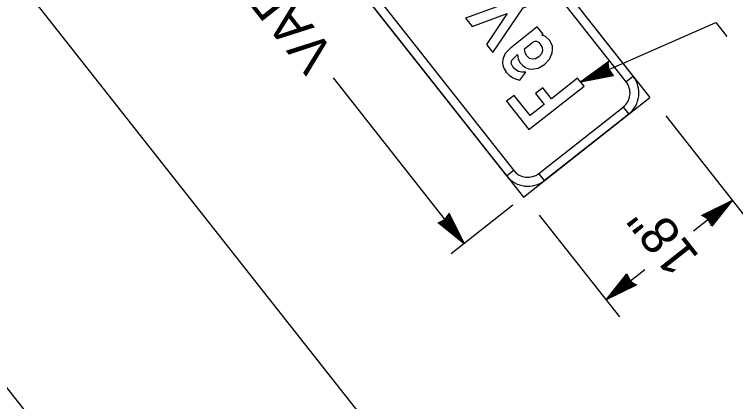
# Model space of a CAD drawing. Extents: x 672126 to 673696, y 1673540 to 1674900.
# Drawn here: x 672217.5 to 672298.2, y 1674587.2 to 1674630.5 of the extents above; entities that cross this region are included whole.
import ezdxf

# ---------------------------------------------------------------- set-up
doc = ezdxf.new("R2010")
doc.units = 0
for name, color, linetype in [('61', 7, 'Continuous'), ('C-ANNO-SYMB', 7, 'Continuous'), ('Level 1', 7, 'Continuous'), ('V-SIGNAL-LOOP', 7, 'Continuous')]:
    doc.layers.add(name, color=color, linetype=linetype)

msp = doc.modelspace()

# ---------------------------------------------------------------- linework, layer by layer
at = {"layer": '61'}
msp.add_lwpolyline([(672259.689, 1674581.406), (672186.159, 1674674.677), (672163.206, 1674656.582), (672236.736, 1674563.312)], close=True, dxfattribs=at)
at = {"layer": 'C-ANNO-SYMB'}
for p, q in [((672247.706, 1674673.092), (672288.567, 1674621.261)), ((672233.571, 1674661.948), (672274.431, 1674610.117)), ((672286.71, 1674623.617), (672285.924, 1674622.998)), ((672274.431, 1674610.117), (672288.567, 1674621.261)), ((672285.592, 1674620.189), (672286.211, 1674619.404)), ((672273.359, 1674613.092), (672272.574, 1674612.473)), ((672276.787, 1674611.975), (672276.168, 1674612.76))]:
    msp.add_line(p, q, dxfattribs=at)
for points in [[(672285.924, 1674622.998), (672248.778, 1674670.117), (672249.564, 1674670.736), (672286.71, 1674623.617), (672285.924, 1674622.998), (672285.924, 1674622.998)], [(672236.213, 1674660.211), (672273.359, 1674613.092), (672272.574, 1674612.473), (672235.428, 1674659.592), (672236.213, 1674660.211), (672236.213, 1674660.211)], [(672276.595, 1674632.098), (672275.794, 1674632.989), (672267.961, 1674630.13), (672268.701, 1674629.191), (672272.617, 1674630.656), (672270.294, 1674627.171), (672270.999, 1674626.277), (672274.405, 1674631.287)], [(672281.214, 1674622.512), (672280.498, 1674623.42), (672277.564, 1674621.108), (672276.59, 1674622.344), (672275.778, 1674621.705), (672276.753, 1674620.468), (672275.182, 1674619.23), (672273.4, 1674621.491), (672272.554, 1674620.824), (672275.052, 1674617.655)], [(672276.168, 1674612.76), (672285.592, 1674620.189), (672286.211, 1674619.404), (672276.787, 1674611.975), (672276.168, 1674612.76), (672276.168, 1674612.76)]]:
    msp.add_lwpolyline(points, close=True, dxfattribs=at)
for points in [[(672276.627, 1674628.33), (672275.99, 1674629.139), (672272.99, 1674626.774), (672272.412, 1674626.18), (672272.115, 1674625.539), (672272.084, 1674625.174), (672272.14, 1674624.814), (672272.287, 1674624.452), (672272.521, 1674624.096), (672272.842, 1674623.755), (672273.203, 1674623.492), (672273.608, 1674623.305), (672274.049, 1674623.194), (672274.704, 1674624.072), (672274.275, 1674624.074), (672273.893, 1674624.162), (672273.57, 1674624.339), (672273.3, 1674624.599), (672273.081, 1674625.036), (672273.147, 1674625.422), (672273.763, 1674626.073), (672273.857, 1674625.529), (672274.072, 1674625.11), (672274.354, 1674624.815), (672274.662, 1674624.603), (672275.005, 1674624.469), (672275.373, 1674624.413), (672276.099, 1674624.536), (672276.805, 1674624.945), (672277.351, 1674625.531), (672277.649, 1674626.235), (672277.705, 1674626.625), (672277.672, 1674626.993), (672277.555, 1674627.339), (672277.35, 1674627.661), (672276.919, 1674628.083), (672276.503, 1674628.233), (672276.627, 1674628.33)], [(672274.573, 1674626.711), (672275.521, 1674627.459), (672275.716, 1674627.557), (672275.914, 1674627.551), (672276.118, 1674627.439), (672276.325, 1674627.223), (672276.536, 1674626.851), (672276.575, 1674626.475), (672276.453, 1674626.122), (672276.169, 1674625.814), (672275.791, 1674625.587), (672275.441, 1674625.523), (672275.121, 1674625.625), (672274.827, 1674625.893), (672274.634, 1674626.263), (672274.573, 1674626.711)]]:
    msp.add_lwpolyline(points, dxfattribs=at)
for centre, radius, start, end in [((672284.354, 1674621.76), 3, 308.25039, 38.2506), ((672284.354, 1674621.76), 2, 308.25039, 38.2506), ((672274.93, 1674614.331), 2, 218.25075, 308.25039), ((672274.93, 1674614.331), 3, 218.25075, 308.25039)]:
    msp.add_arc(centre, radius, start, end, dxfattribs=at)
at = {"layer": 'Level 1'}
for p, q in [((672283.973, 1674625.266), (672280.853, 1674622.996)), ((672283.794, 1674624.956), (672281.211, 1674623.102)), ((672283.837, 1674625.12), (672281.368, 1674623.201)), ((672283.802, 1674624.815), (672281.761, 1674623.409)), ((672283.802, 1674624.815), (672281.904, 1674623.415)), ((672283.875, 1674624.904), (672283.794, 1674624.956)), ((672284.052, 1674624.068), (672283.802, 1674624.815)), ((672284.103, 1674623.887), (672283.802, 1674624.815)), ((672283.857, 1674624.755), (672283.837, 1674625.12)), ((672284.019, 1674624.397), (672283.857, 1674624.755)), ((672283.921, 1674625.127), (672283.875, 1674624.904)), ((672284.027, 1674624.314), (672283.921, 1674625.127)), ((672281.761, 1674623.409), (672284.004, 1674623.986)), ((672282.299, 1674623.62), (672282.686, 1674623.909)), ((672283.77, 1674624.629), (672282.406, 1674623.641)), ((672282.406, 1674623.641), (672283.85, 1674624.004)), ((672282.982, 1674623.956), (672282.775, 1674623.778)), ((672283.729, 1674624.467), (672282.825, 1674623.858)), ((672282.825, 1674623.858), (672283.721, 1674624.032)), ((672283.889, 1674624.05), (672282.982, 1674623.956)), ((672283.723, 1674624.349), (672283.243, 1674624.018)), ((672283.243, 1674624.018), (672283.667, 1674624.095)), ((672283.648, 1674624.198), (672283.824, 1674624.509)), ((672283.667, 1674624.095), (672283.648, 1674624.198)), ((672283.721, 1674624.032), (672283.723, 1674624.349)), ((672283.85, 1674624.004), (672283.729, 1674624.467)), ((672284.004, 1674623.986), (672283.77, 1674624.629)), ((672283.824, 1674624.509), (672283.889, 1674624.05)), ((672284.509, 1674623.696), (672284.019, 1674624.397)), ((672284.369, 1674623.749), (672284.027, 1674624.314)), ((672284.218, 1674623.825), (672284.052, 1674624.068)), ((672267.807, 1674604.895), (672253.192, 1674623.434)), ((672280.853, 1674622.996), (672284.509, 1674623.696)), ((672281.164, 1674623.079), (672284.369, 1674623.749)), ((672281.368, 1674623.201), (672281.164, 1674623.079)), ((672281.211, 1674623.102), (672281.334, 1674623.271)), ((672281.334, 1674623.271), (672282.082, 1674623.781)), ((672281.571, 1674623.262), (672284.218, 1674623.825)), ((672282.082, 1674623.781), (672281.571, 1674623.262)), ((672281.904, 1674623.415), (672284.103, 1674623.887)), ((672282.775, 1674623.778), (672282.299, 1674623.62)), ((672290.346, 1674619.218), (672299.175, 1674608.019)), ((672293.467, 1674606.332), (672297.807, 1674609.753)), ((672294.346, 1674608.05), (672297.807, 1674609.753)), ((672294.538, 1674608.102), (672297.387, 1674609.394)), ((672294.704, 1674608.064), (672297.548, 1674609.486)), ((672297.807, 1674609.753), (672295.486, 1674606.845)), ((672297.59, 1674609.518), (672295.504, 1674606.993)), ((672297.34, 1674609.456), (672296.541, 1674609.032)), ((672297.548, 1674609.486), (672297.34, 1674609.456)), ((672297.387, 1674609.394), (672297.59, 1674609.518)), ((672273.267, 1674609.2), (672266.363, 1674603.757)), ((672294.825, 1674607.992), (672297.019, 1674609.142)), ((672294.825, 1674607.992), (672296.948, 1674609.019)), ((672295.004, 1674607.933), (672296.514, 1674608.679)), ((672297.019, 1674609.142), (672295.464, 1674607.427)), ((672296.948, 1674609.019), (672295.505, 1674607.293)), ((672297.238, 1674609.242), (672295.507, 1674607.162)), ((672296.514, 1674608.679), (672295.52, 1674607.571)), ((672296.582, 1674608.765), (672296.146, 1674608.557)), ((672296.22, 1674608.417), (672296.582, 1674608.765)), ((672296.541, 1674609.032), (672297.238, 1674609.242)), ((672265.347, 1674607.197), (672266.046, 1674607.878)), ((672265.476, 1674607.334), (672266.046, 1674607.878)), ((672265.613, 1674607.539), (672266.086, 1674608.21)), ((672265.658, 1674607.609), (672265.968, 1674607.85)), ((672265.968, 1674607.85), (672266.156, 1674608.165)), ((672266.086, 1674608.21), (672266.022, 1674607.991)), ((672266.022, 1674607.991), (672266.118, 1674607.999)), ((672266.046, 1674607.878), (672267.072, 1674605.755)), ((672266.046, 1674607.878), (672267.196, 1674605.683)), ((672266.104, 1674608.357), (672267.807, 1674604.895)), ((672266.118, 1674607.999), (672267.54, 1674605.155)), ((672266.156, 1674608.165), (672267.448, 1674605.316)), ((672276.21, 1674608.074), (672285.166, 1674596.714)), ((672295.163, 1674607.559), (672294.493, 1674608.032)), ((672294.493, 1674608.032), (672294.712, 1674607.968)), ((672294.852, 1674607.914), (672294.538, 1674608.102)), ((672294.712, 1674607.968), (672294.704, 1674608.064)), ((672295.369, 1674607.422), (672294.825, 1674607.992)), ((672295.505, 1674607.293), (672294.825, 1674607.992)), ((672295.094, 1674607.604), (672294.852, 1674607.914)), ((672295.464, 1674607.427), (672295.004, 1674607.933)), ((672295.443, 1674607.84), (672295.085, 1674607.83)), ((672295.085, 1674607.83), (672295.461, 1674607.559)), ((672295.166, 1674607.893), (672296.127, 1674608.41)), ((672295.52, 1674607.571), (672295.166, 1674607.893)), ((672295.274, 1674607.844), (672295.791, 1674608.115)), ((672295.555, 1674607.698), (672295.274, 1674607.844)), ((672295.525, 1674607.775), (672295.443, 1674607.84)), ((672295.461, 1674607.559), (672295.967, 1674608.317)), ((672295.791, 1674608.115), (672295.525, 1674607.775)), ((672296.127, 1674608.41), (672295.555, 1674607.698)), ((672295.967, 1674608.317), (672296.22, 1674608.417)), ((672264.899, 1674607.217), (672265.658, 1674607.609)), ((672267.807, 1674604.895), (672264.899, 1674607.217)), ((672265.047, 1674607.199), (672265.613, 1674607.539)), ((672267.571, 1674605.113), (672265.047, 1674607.199)), ((672265.216, 1674607.196), (672265.476, 1674607.334)), ((672267.296, 1674605.465), (672265.216, 1674607.196)), ((672267.072, 1674605.755), (672265.347, 1674607.197)), ((672265.481, 1674607.239), (672265.987, 1674607.699)), ((672267.196, 1674605.683), (672265.481, 1674607.239)), ((672265.884, 1674607.618), (672265.613, 1674607.242)), ((672265.613, 1674607.242), (672266.371, 1674606.736)), ((672265.625, 1674607.183), (672265.947, 1674607.537)), ((672266.733, 1674606.189), (672265.625, 1674607.183)), ((672265.752, 1674607.148), (672265.898, 1674607.429)), ((672266.464, 1674606.576), (672265.752, 1674607.148)), ((672265.829, 1674607.178), (672265.894, 1674607.26)), ((672266.169, 1674606.912), (672265.829, 1674607.178)), ((672265.894, 1674607.26), (672265.884, 1674607.618)), ((672265.898, 1674607.429), (672266.169, 1674606.912)), ((672265.947, 1674607.537), (672266.464, 1674606.576)), ((672265.987, 1674607.699), (672266.733, 1674606.189)), ((672295.486, 1674606.845), (672295.094, 1674607.604)), ((672295.504, 1674606.993), (672295.163, 1674607.559)), ((672295.507, 1674607.162), (672295.369, 1674607.422)), ((672266.371, 1674606.736), (672266.471, 1674606.482)), ((672266.471, 1674606.482), (672266.819, 1674606.121)), ((672266.819, 1674606.121), (672266.611, 1674606.556)), ((672267.51, 1674605.363), (672267.085, 1674606.162)), ((672267.085, 1674606.162), (672267.296, 1674605.465)), ((672267.54, 1674605.155), (672267.51, 1674605.363)), ((672267.448, 1674605.316), (672267.571, 1674605.113)), ((672283.672, 1674598.61), (672287.997, 1674602.019)), ((672283.672, 1674598.61), (672285.993, 1674601.518)), ((672283.89, 1674598.846), (672285.975, 1674601.37)), ((672285.975, 1674601.37), (672286.316, 1674600.804)), ((672285.993, 1674601.518), (672286.385, 1674600.759)), ((672284.241, 1674599.121), (672285.972, 1674601.201)), ((672284.46, 1674599.221), (672286.015, 1674600.936)), ((672284.531, 1674599.345), (672285.974, 1674601.07)), ((672284.965, 1674599.684), (672285.96, 1674600.792)), ((672285.353, 1674599.953), (672285.924, 1674600.665)), ((672286.018, 1674600.804), (672285.512, 1674600.046)), ((672285.688, 1674600.248), (672285.954, 1674600.588)), ((672286.205, 1674600.519), (672285.688, 1674600.248)), ((672285.924, 1674600.665), (672286.205, 1674600.519)), ((672285.954, 1674600.588), (672286.036, 1674600.523)), ((672285.96, 1674600.792), (672286.313, 1674600.47)), ((672285.972, 1674601.201), (672286.11, 1674600.941)), ((672285.974, 1674601.07), (672286.654, 1674600.371)), ((672286.015, 1674600.936), (672286.475, 1674600.43)), ((672286.394, 1674600.533), (672286.018, 1674600.804)), ((672286.036, 1674600.523), (672286.394, 1674600.533)), ((672286.11, 1674600.941), (672286.654, 1674600.371)), ((672286.316, 1674600.804), (672286.986, 1674600.331)), ((672286.385, 1674600.759), (672286.627, 1674600.449)), ((672287.133, 1674600.313), (672283.672, 1674598.61)), ((672286.776, 1674600.299), (672283.932, 1674598.877)), ((672286.941, 1674600.261), (672284.092, 1674598.969)), ((672286.654, 1674600.371), (672284.46, 1674599.221)), ((672286.654, 1674600.371), (672284.531, 1674599.345)), ((672285.259, 1674599.946), (672284.897, 1674599.598)), ((672284.897, 1674599.598), (672285.333, 1674599.806)), ((672286.475, 1674600.43), (672284.965, 1674599.684)), ((672285.512, 1674600.046), (672285.259, 1674599.946)), ((672286.313, 1674600.47), (672285.353, 1674599.953)), ((672286.627, 1674600.449), (672286.941, 1674600.261)), ((672286.986, 1674600.331), (672286.767, 1674600.395)), ((672286.767, 1674600.395), (672286.776, 1674600.299)), ((672284.092, 1674598.969), (672283.89, 1674598.846)), ((672283.932, 1674598.877), (672284.139, 1674598.907)), ((672284.139, 1674598.907), (672284.938, 1674599.332)), ((672284.938, 1674599.332), (672284.241, 1674599.121))]:
    msp.add_line(p, q, dxfattribs=at)
msp.add_lwpolyline([(672280.853, 1674622.996), (672295.961, 1674629.633), (672297.184, 1674628.083)], dxfattribs=at)
at = {"layer": 'V-SIGNAL-LOOP'}
msp.add_lwpolyline([(672292.36, 1674628.454), (672292.36, 1674628.454), (672292.36, 1674628.454)], dxfattribs=at)

# ---------------------------------------------------------------- texts
at = {"layer": 'Level 1'}
for s, p in [('VAR.', (672253.453, 1674626.153)), ('18"', (672294.216, 1674603.448))]:
    msp.add_text(s, height=4.2, rotation=128.25054, dxfattribs=at).set_placement(p)

doc.saveas('drawing.dxf')
